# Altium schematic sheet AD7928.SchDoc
size A
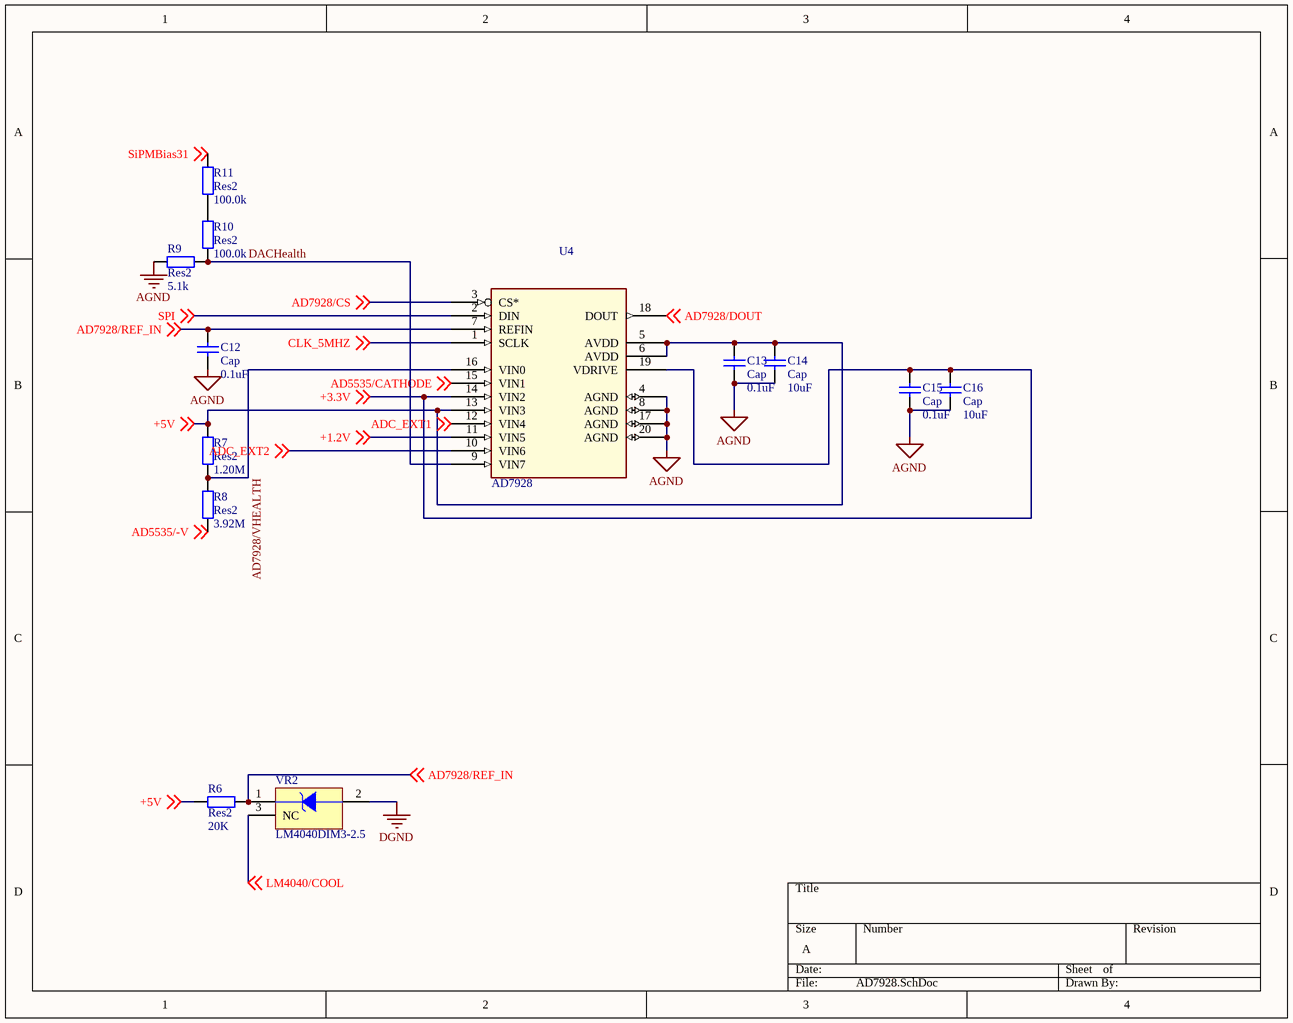
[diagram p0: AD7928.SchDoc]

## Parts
C12  Cap  value 0.1uF  [0402]
C13  Cap  value 0.1uF  [0402]
C14  Cap  value 10uF  [C1206]
C15  Cap  value 0.1uF  [0402]
C16  Cap  value 10uF  [C1206]
R6  Res2  value 20K  [3216[1206]]
R7  Res2  value 1.20M  [2012[0805]]
R8  Res2  value 3.92M  [2012[0805]]
R9  Res2  value 5.1k  [2012[0805]]
R10  Res2  value 100.0k  [2012[0805]]
R11  Res2  value 100.0k  [2012[0805]]
U4  AD7928  [RU-20]
VR2  LM4040DIM3-2.5  [M03B]

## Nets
AGND: C12.1 C13.1 C14.1 C15.1 C16.1 R9.2 U4.4(AGND) U4.8(AGND) U4.17(AGND) U4.20(AGND)
DGND: VR2.2(V-)
+1.2V: U4.11(VIN5) ; off-sheet +1.2V
+3.3V: C15.2 C16.2 U4.14(VIN2) U4.19(VDRIVE) ; off-sheet +3.3V
+5V: C13.2 C14.2 R6.1 R7.2 U4.5(AVDD) U4.6(AVDD) U4.13(VIN3) ; off-sheet +5V
AD5535/-V: R8.1 ; off-sheet AD5535/-V
AD5535/CATHODE: U4.15(VIN1) ; off-sheet AD5535/CATHODE
AD7928/CS: U4.3(CS*) ; off-sheet AD7928/CS
AD7928/DOUT: U4.18(DOUT) ; off-sheet AD7928/DOUT
AD7928/REF_IN: C12.2 R6.2 U4.7(REFIN) VR2.1(V+) ; off-sheet AD7928/REF_IN
AD7928/VHEALTH: R7.1 R8.2 U4.16(VIN0)
ADC_EXT1: U4.12(VIN4) ; off-sheet ADC_EXT1
ADC_EXT2: U4.10(VIN6) ; off-sheet ADC_EXT2
CLK_5MHZ: U4.1(SCLK) ; off-sheet CLK_5MHZ
DACHealth: R9.1 R10.1 U4.9(VIN7)
LM4040/COOL: VR2.3(NC) ; off-sheet LM4040/COOL
SiPMBias31: R11.2 ; off-sheet SiPMBias31
SPI: U4.2(DIN) ; off-sheet SPI
NetR10_2: R10.2 R11.1

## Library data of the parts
C12-C16 = Cap: Capacitor
R6-R11 = Res2: Resistor
U4 = AD7928BRU-REEL7: SlotXofY: SYM 1 OF 1
VR2 = LM4040DIM3-2.5: Precision Micropower Shunt Voltage Reference; Note: Pin 3 must be left floating or connected to pin 2.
